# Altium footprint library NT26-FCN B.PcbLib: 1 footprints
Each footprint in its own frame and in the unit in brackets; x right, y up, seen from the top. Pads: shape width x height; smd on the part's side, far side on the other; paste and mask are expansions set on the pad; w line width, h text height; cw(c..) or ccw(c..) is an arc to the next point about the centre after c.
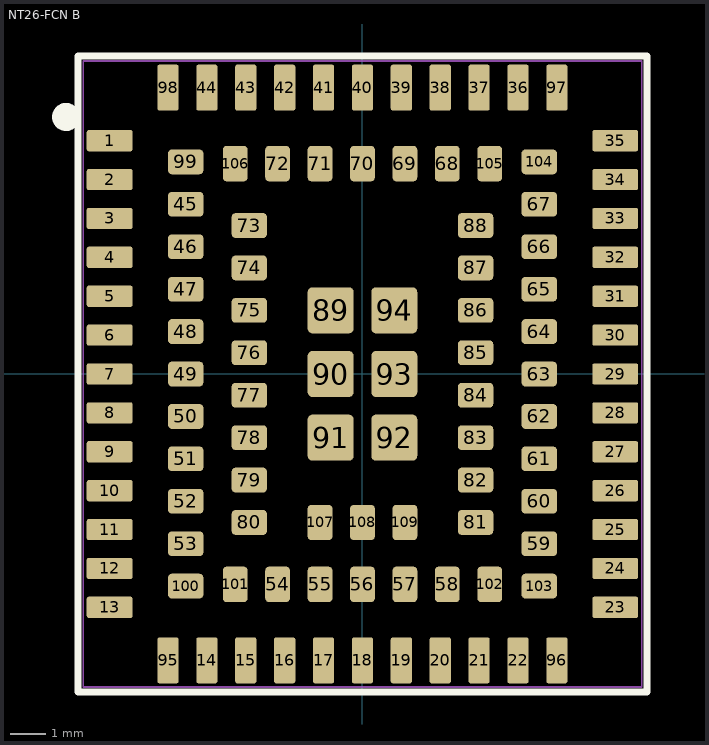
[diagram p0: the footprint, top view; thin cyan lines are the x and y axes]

## NT26-FCN B [mm]
pads (109):
  rrect20% 1.3x0.6 smd mask+0.076: 1(-7.15,6.6) 2(-7.15,5.5) 3(-7.15,4.4) 4(-7.15,3.3) 5(-7.15,2.2) 6(-7.15,1.1) 7(-7.15,0) 8(-7.15,-1.1) 9(-7.15,-2.2) 10(-7.15,-3.3) 11(-7.15,-4.4) 12(-7.15,-5.5) 13(-7.15,-6.6) 23(7.15,-6.6) 24(7.15,-5.5) 25(7.15,-4.4) 26(7.15,-3.3) 27(7.15,-2.2) 28(7.15,-1.1) 29(7.15,0) 30(7.15,1.1) 31(7.15,2.2) 32(7.15,3.3) 33(7.15,4.4) 34(7.15,5.5) 35(7.15,6.6)
  rrect20% 0.6x1.3 smd mask+0.076: 14(-4.4,-8.1) 15(-3.3,-8.1) 16(-2.2,-8.1) 17(-1.1,-8.1) 18(0,-8.1) 19(1.1,-8.1) 20(2.2,-8.1) 21(3.3,-8.1) 22(4.4,-8.1) 36(4.4,8.1) 37(3.3,8.1) 38(2.2,8.1) 39(1.1,8.1) 40(0,8.1) 41(-1.1,8.1) 42(-2.2,8.1) 43(-3.3,8.1) 44(-4.4,8.1) 95(-5.5,-8.1) 96(5.5,-8.1) 97(5.5,8.1) 98(-5.5,8.1)
  rrect30% 1x0.7 smd mask+0.064: 45(-5,4.8) 46(-5,3.6) 47(-5,2.4) 48(-5,1.2) 49(-5,0) 50(-5,-1.2) 51(-5,-2.4) 52(-5,-3.6) 53(-5,-4.8) 59(5,-4.8) 60(5,-3.6) 61(5,-2.4) 62(5,-1.2) 63(5,0) 64(5,1.2) 65(5,2.4) 66(5,3.6) 67(5,4.8) 73(-3.2,4.2) 74(-3.2,3) 75(-3.2,1.8) 76(-3.2,0.6) 77(-3.2,-0.6) 78(-3.2,-1.8) 79(-3.2,-3) 80(-3.2,-4.2) 81(3.2,-4.2) 82(3.2,-3) 83(3.2,-1.8) 84(3.2,-0.6) 85(3.2,0.6) 86(3.2,1.8) 87(3.2,3) 88(3.2,4.2) 99(-5,6) 100(-5,-6) 103(5,-6) 104(5,6)
  rrect30% 0.7x1 smd mask+0.064: 54(-2.4,-5.95) 55(-1.2,-5.95) 56(0,-5.95) 57(1.2,-5.95) 58(2.4,-5.95) 68(2.4,5.95) 69(1.2,5.95) 70(0,5.95) 71(-1.2,5.95) 72(-2.4,5.95) 101(-3.6,-5.95) 102(3.6,-5.95) 105(3.6,5.95) 106(-3.6,5.95) 107(-1.2,-4.2) 108(0,-4.2) 109(1.2,-4.2)
  rrect20% 1.3x1.3 smd mask+0.064: 89(-0.9,1.8) 90(-0.9,0) 91(-0.9,-1.8) 92(0.9,-1.8) 93(0.9,0) 94(0.9,1.8)
Top Overlay:
  circle w0.5: c-8.383,7.27 r0.145
  lines w0.198: -8.05,-9 8.05,-9 8.05,9 -8.05,9 -8.05,-9
Mechanical 1:
  lines w0.05: -7.9,-8.85 7.9,-8.85 7.9,8.85 -7.9,8.85 -7.9,-8.85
